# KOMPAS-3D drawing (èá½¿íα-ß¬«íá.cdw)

Referenced files: Калибр-скоба.cdw
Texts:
  Калибр-скоба
  http://freecads.ru/
  Текст на чертеже
  Размерные надписи
  Шероховатость
  Линия выноски #1
  Линия выноски #2
  Линия выноски #3
  Отклонения формы и база
  Заголовок таблицы
  Ячейка таблицы
  Стрелка вида
  Обозначение изменения
  Фигурная скобка
  Номер узла
  Марка координационной оси
  VRCB
  Выносная надпись
  Обозначение узла
  Марка/позиционное обозначение с линией-выноской
  Марка/позиционное обозначение на линии
  Марка/позиционное обозначение без линии-выноски
  Ra 3,2
  изн. 50,141
  Ra 0,16
  2. Неуказанные предельные отклонения  IT12 2 .
  3. Покрытие нерабочих поверхностей - Хим.Фос.прм.
  4. Маркировать обозначение калибра-скобы по ГОСТ 2015-84.
  5. Остальные т.т. по ГОСТ 2015-84.
  Ra 6,3
  Сталь У8 ГОСТ1435-91
Dimensions and other numbers on the sheet: 7; 100; 6; 24; 10; 44; 4,5; 2 отв.; 31; 25; 3; 15; 50,062; 50,095; 120; 1; 0,6; 1. 59...65 HRC.; 0,3; 1:1; 0; 2; 4; 5; 8; 9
